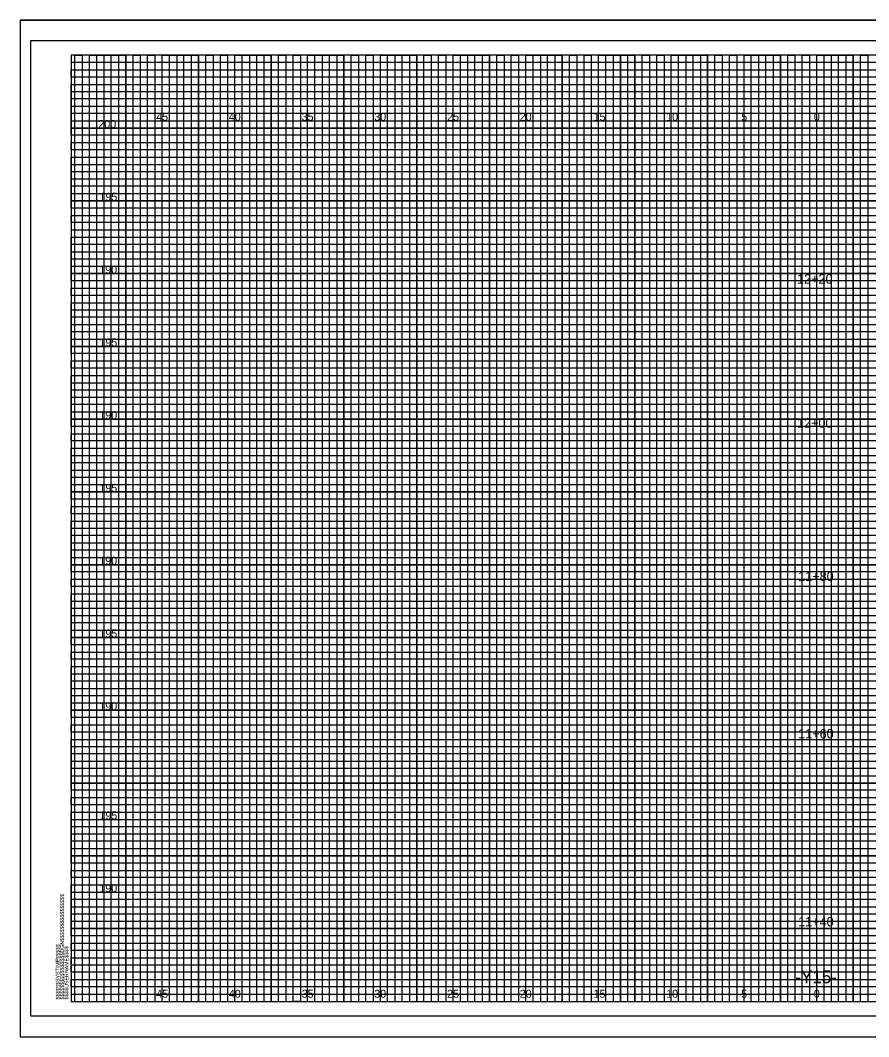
# Model space of a CAD drawing. Extents: x -4 to 103, y -2 to 67.
# Drawn here: x -3.5 to 54.8, y -2.4 to 67.4 of the extents above; entities that cross this region are included whole.
import ezdxf

# ---------------------------------------------------------------- set-up
doc = ezdxf.new("R2010")
doc.units = 0
for name, color, linetype in [('Exist XS Ground Line', 7, 'Continuous'), ('Old_Level_10', 7, 'Continuous'), ('Old_Level_16', 7, 'Continuous'), ('Old_Level_3', 7, 'Continuous'), ('Old_Level_5', 7, 'Continuous'), ('Old_Level_8', 7, 'Continuous'), ('Prop XS Dump Level', 7, 'Continuous'), ('Prop XS EOT Tick Mark', 7, 'Continuous'), ('Prop XS Finish Grade', 7, 'Continuous'), ('Prop XS Side Slope Text', 7, 'Continuous'), ('Prop XS Suitable Common Exc Shape', 7, 'Continuous')]:
    doc.layers.add(name, color=color, linetype=linetype)

msp = doc.modelspace()

# ---------------------------------------------------------------- linework, layer by layer
at = {"layer": 'Exist XS Ground Line'}
msp.add_lwpolyline([(103, 66), (-2.8, 66), (-2.8, -1), (103, -1)], close=True, dxfattribs=at)
at = {"layer": 'Old_Level_10'}
for p, q in [((1.25, 0), (1.25, 65)), ((3.75, 0), (3.75, 65)), ((6.25, 0), (6.25, 65)), ((8.75, 0), (8.75, 65)), ((11.25, 0), (11.25, 65)), ((13.75, 0), (13.75, 65)), ((16.25, 0), (16.25, 65)), ((18.75, 0), (18.75, 65)), ((21.25, 0), (21.25, 65)), ((23.75, 0), (23.75, 65)), ((26.25, 0), (26.25, 65)), ((28.75, 0), (28.75, 65)), ((31.25, 0), (31.25, 65)), ((33.75, 0), (33.75, 65)), ((36.25, 0), (36.25, 65)), ((38.75, 0), (38.75, 65)), ((41.25, 0), (41.25, 65)), ((43.75, 0), (43.75, 65)), ((46.25, 0), (46.25, 65)), ((48.75, 0), (48.75, 65)), ((51.25, 0), (51.25, 65)), ((53.75, 0), (53.75, 65)), ((0, 62.5), (74.25, 62.5)), ((0, 60), (102.5, 60)), ((0, 57.5), (102.5, 57.5)), ((0, 55), (102.5, 55)), ((0, 52.5), (102.5, 52.5)), ((0, 50), (102.5, 50)), ((0, 47.5), (102.5, 47.5)), ((0, 45), (102.5, 45)), ((0, 42.5), (102.5, 42.5)), ((0, 40), (102.5, 40)), ((0, 37.5), (102.5, 37.5)), ((0, 35), (102.5, 35)), ((0, 32.5), (102.5, 32.5)), ((0, 30), (102.5, 30)), ((0, 27.5), (102.5, 27.5)), ((0, 25), (102.5, 25)), ((0, 22.5), (102.5, 22.5)), ((0, 20), (102.5, 20)), ((0, 17.5), (102.5, 17.5)), ((0, 15), (102.5, 15)), ((0, 12.5), (102.5, 12.5)), ((0, 10), (102.5, 10)), ((0, 7.5), (102.5, 7.5)), ((0, 5), (102.5, 5)), ((0, 2.5), (102.5, 2.5))]:
    msp.add_line(p, q, dxfattribs=at)
at = {"layer": 'Old_Level_3'}
for p, q in [((-3.5, 67.4), (103.4, 67.4)), ((-3.5, 67.4), (-3.5, -2.425)), ((-3.5, -2.425), (103.4, -2.425))]:
    msp.add_line(p, q, dxfattribs=at)
at = {"layer": 'Old_Level_5'}
msp.add_lwpolyline([(103.4, 67.4), (-3.5, 67.4), (-3.5, -2.425), (103.4, -2.425)], close=True, dxfattribs=at)
at = {"layer": 'Old_Level_8'}
for points in [[(1.25, 0), (1.25, 65), (3.75, 65), (3.75, 0), (6.25, 0), (6.25, 65), (8.75, 65), (8.75, 0), (11.25, 0), (11.25, 65), (13.75, 65), (13.75, 0), (16.25, 0), (16.25, 65), (18.75, 65), (18.75, 0), (21.25, 0), (21.25, 65), (23.75, 65), (23.75, 0), (26.25, 0), (26.25, 65), (28.75, 65), (28.75, 0), (31.25, 0), (31.25, 65), (33.75, 65), (33.75, 0), (36.25, 0), (36.25, 65), (38.75, 65), (38.75, 0), (41.25, 0), (41.25, 65), (43.75, 65), (43.75, 0), (46.25, 0), (46.25, 65), (48.75, 65), (48.75, 0), (51.25, 0), (51.25, 65), (53.75, 65), (53.75, 0)], [(102.5, 60), (0, 60), (0, 62.5), (74.25, 62.5)], [(102.5, 55), (0, 55), (0, 57.5), (102.5, 57.5)], [(102.5, 50), (0, 50), (0, 52.5), (102.5, 52.5)], [(102.5, 45), (0, 45), (0, 47.5), (102.5, 47.5)], [(102.5, 40), (0, 40), (0, 42.5), (102.5, 42.5)], [(102.5, 35), (0, 35), (0, 37.5), (102.5, 37.5)], [(102.5, 30), (0, 30), (0, 32.5), (102.5, 32.5)], [(102.5, 25), (0, 25), (0, 27.5), (102.5, 27.5)], [(102.5, 20), (0, 20), (0, 22.5), (102.5, 22.5)], [(102.5, 15), (0, 15), (0, 17.5), (102.5, 17.5)], [(102.5, 10), (0, 10), (0, 12.5), (102.5, 12.5)], [(102.5, 5), (0, 5), (0, 7.5), (102.5, 7.5)], [(0, 2.5), (102.5, 2.5)]]:
    msp.add_lwpolyline(points, dxfattribs=at)
at = {"layer": 'Prop XS Dump Level'}
msp.add_lwpolyline([(102.5, 65), (0, 65), (0, 0), (102.5, 0)], close=True, dxfattribs=at)
at = {"layer": 'Prop XS Finish Grade'}
for points in [[(0.25, 0), (0.25, 65), (0.75, 65), (0.75, 0), (1.75, 0), (1.75, 65), (2.25, 65), (2.25, 0), (2.75, 0), (2.75, 65), (3.25, 65), (3.25, 0), (4.25, 0), (4.25, 65), (4.75, 65), (4.75, 0), (5.25, 0), (5.25, 65), (5.75, 65), (5.75, 0), (6.75, 0), (6.75, 65), (7.25, 65), (7.25, 0), (7.75, 0), (7.75, 65), (8.25, 65), (8.25, 0), (9.25, 0), (9.25, 65), (9.75, 65), (9.75, 0), (10.25, 0), (10.25, 65), (10.75, 65), (10.75, 0), (11.75, 0), (11.75, 65), (12.25, 65), (12.25, 0), (12.75, 0), (12.75, 65), (13.25, 65), (13.25, 0), (14.25, 0), (14.25, 65), (14.75, 65), (14.75, 0), (15.75, 0), (15.25, 0), (15.25, 65), (15.75, 65), (15.75, 0), (16.75, 0), (16.75, 65), (17.25, 65), (17.25, 0), (17.75, 0), (17.75, 65), (18.25, 65), (18.25, 0), (19.25, 0), (19.25, 65), (19.75, 65), (19.75, 0), (20.25, 0), (20.25, 65), (20.75, 65), (20.75, 0), (21.75, 0), (21.75, 65), (22.25, 65), (22.25, 0), (22.75, 0), (22.75, 65), (23.25, 65), (23.25, 0), (24.25, 0), (24.25, 65), (24.75, 65), (24.75, 0), (25.25, 0), (25.25, 65), (25.75, 65), (25.75, 0), (26.75, 0), (26.75, 65), (27.25, 65), (27.25, 0), (27.75, 0), (27.75, 65), (28.25, 65), (28.25, 0), (29.25, 0), (29.25, 65), (29.75, 65), (29.75, 0), (30.25, 0), (30.25, 65), (30.75, 65), (30.75, 0)], [(30.75, 0), (31.75, 0), (31.75, 65), (32.25, 65), (32.25, 0), (32.75, 0), (32.75, 65), (33.25, 65), (33.25, 0), (34.25, 0), (34.25, 65), (34.75, 65), (34.75, 0), (35.25, 0), (35.25, 65), (35.75, 65), (35.75, 0), (36.75, 0), (36.75, 65), (37.25, 65), (37.25, 0), (37.75, 0), (37.75, 65), (37.75, 0)], [(38.25, 65), (38.25, 0), (39.25, 0), (39.25, 65), (39.75, 65), (39.75, 0), (40.25, 0), (40.25, 65), (40.75, 65), (40.75, 0), (41.75, 0), (41.75, 65), (42.25, 65), (42.25, 0), (42.75, 0), (42.75, 65), (43.25, 65), (43.25, 0), (43.75, 0), (44.25, 0), (44.25, 65), (44.75, 65), (44.75, 0), (45.25, 0), (45.25, 65), (45.75, 65), (45.75, 0), (46.75, 0), (46.75, 65), (47.25, 65), (47.25, 0), (47.75, 0), (47.75, 65), (48.25, 65), (48.25, 0), (49.25, 0), (49.25, 65), (49.75, 65), (49.75, 0), (50.25, 0), (50.25, 65), (50.75, 65), (50.75, 0), (51.75, 0), (51.75, 65), (52.25, 65), (52.25, 0), (52.75, 0), (52.75, 65), (53.25, 65), (53.25, 0), (54.25, 0), (54.25, 65), (54.75, 65), (54.75, 0), (55.25, 0)], [(0, 62), (0, 63), (74.25, 63), (74.25, 63.5), (0, 63.5), (0, 64), (74.25, 64), (74.25, 64.5), (0, 64.5)], [(102.5, 62), (0, 62)], [(102.5, 61), (0, 61), (0, 61.5), (102.5, 61.5)], [(102.5, 59.5), (0, 59.5), (0, 60.5), (102.5, 60.5)], [(102.5, 58.5), (0, 58.5), (0, 59), (102.5, 59)], [(102.5, 57), (0, 57), (0, 58), (102.5, 58)], [(102.5, 56), (0, 56), (0, 56.5), (102.5, 56.5)], [(102.5, 54.5), (0, 54.5), (0, 55.5), (102.5, 55.5)], [(102.5, 53.5), (0, 53.5), (0, 54), (102.5, 54)], [(0, 53), (102.5, 53)], [(102.5, 52), (0, 52)], [(102.5, 51), (0, 51), (0, 51.5), (102.5, 51.5)], [(102.5, 49.5), (0, 49.5), (0, 50.5), (102.5, 50.5)], [(102.5, 48.5), (0, 48.5), (0, 49), (102.5, 49)], [(102.5, 47), (0, 47), (0, 48), (102.5, 48)], [(102.5, 46), (0, 46), (0, 46.5), (102.5, 46.5)], [(102.5, 44.5), (0, 44.5), (0, 45.5), (102.5, 45.5)], [(102.5, 43.5), (0, 43.5), (0, 44), (102.5, 44)], [(102.5, 42), (0, 42), (0, 43), (102.5, 43)], [(102.5, 41), (0, 41), (0, 41.5), (102.5, 41.5)], [(102.5, 39.5), (0, 39.5), (0, 40.5), (102.5, 40.5)], [(102.5, 38.5), (0, 38.5), (0, 39), (102.5, 39)], [(102.5, 37), (0, 37), (0, 38), (102.5, 38)], [(102.5, 36), (0, 36), (0, 36.5), (102.5, 36.5)], [(102.5, 34.5), (0, 34.5), (0, 35.5), (102.5, 35.5)], [(102.5, 33.5), (0, 33.5), (0, 34), (102.5, 34)], [(102.5, 32), (0, 32), (0, 33), (102.5, 33)], [(102.5, 31), (0, 31), (0, 31.5)], [(0, 31.5), (102.5, 31.5)], [(102.5, 29.5), (0, 29.5), (0, 30.5), (102.5, 30.5)], [(102.5, 28.5), (0, 28.5), (0, 29), (102.5, 29)], [(102.5, 27), (0, 27), (0, 28), (102.5, 28)], [(102.5, 26), (0, 26), (0, 26.5), (102.5, 26.5)], [(102.5, 24.5), (0, 24.5), (0, 25.5), (102.5, 25.5)], [(102.5, 23.5), (0, 23.5), (0, 24), (102.5, 24)], [(102.5, 22), (0, 22), (0, 23), (102.5, 23)], [(102.5, 21), (0, 21), (0, 21.5), (102.5, 21.5)], [(102.5, 19.5), (0, 19.5), (0, 20.5), (102.5, 20.5)], [(102.5, 18.5), (0, 18.5), (0, 19), (102.5, 19)], [(102.5, 17), (0, 17), (0, 18), (102.5, 18)], [(102.5, 16), (0, 16), (0, 16.5), (102.5, 16.5)], [(102.5, 14.5), (0, 14.5), (0, 15.5), (102.5, 15.5)], [(102.5, 13.5), (0, 13.5), (0, 14), (102.5, 14)], [(102.5, 12), (0, 12), (0, 13), (102.5, 13)], [(102.5, 11), (0, 11), (0, 11.5), (102.5, 11.5)], [(102.5, 9.5), (0, 9.5), (0, 10.5), (102.5, 10.5)], [(102.5, 8.5), (0, 8.5), (0, 9), (102.5, 9)], [(102.5, 7), (0, 7), (0, 8), (102.5, 8)], [(102.5, 6), (0, 6), (0, 6.5), (102.5, 6.5)], [(102.5, 4.5), (0, 4.5), (0, 5.5), (102.5, 5.5)], [(102.5, 3.5), (0, 3.5), (0, 4), (102.5, 4)], [(102.5, 2), (0, 2), (0, 3), (102.5, 3)], [(102.5, 1), (0, 1), (0, 1.5), (102.5, 1.5)], [(0, 0.5), (102.5, 0.5)]]:
    msp.add_lwpolyline(points, dxfattribs=at)

# ---------------------------------------------------------------- texts
at = {"layer": 'Old_Level_16'}
for s, p in [('45', (5.8399, 60.5)), ('40', (10.8313, 60.5)), ('35', (15.8399, 60.5)), ('30', (20.8313, 60.5)), ('25', (25.8399, 60.5)), ('20', (30.8313, 60.5)), ('15', (35.9058, 60.5)), ('10', (40.8971, 60.5)), ('5', (46.0574, 60.5)), ('0', (51.0488, 60.5)), ('0', (51.0488, 60.5)), ('45', (5.8399, 0.25)), ('40', (10.8313, 0.25)), ('35', (15.8399, 0.25)), ('30', (20.8313, 0.25)), ('25', (25.8399, 0.25)), ('20', (30.8313, 0.25)), ('15', (35.9058, 0.25)), ('10', (40.8971, 0.25)), ('5', (46.0574, 0.25)), ('0', (51.0488, 0.25)), ('0', (51.0488, 0.25))]:
    msp.add_text(s, height=0.55, dxfattribs=at).set_placement(p)
at = {"layer": 'Old_Level_8'}
msp.add_text('040397', height=0.0025, rotation=90, dxfattribs=at).set_placement((-0.0007, 64.9864))
at = {"layer": 'Prop XS Dump Level'}
for s, p in [('$$$$$$$$$$$$$$$$DGN$$$$$$$$$$$$$$$$', (-0.5, 0.125)), ('$$$$$$SYSTIME$$$$$', (-0.7973, 0.1247)), ('$$$$USERNAME$$$$', (-0.2, 0.125))]:
    msp.add_text(s, height=0.2625, rotation=90, dxfattribs=at).set_placement(p)
at = {"layer": 'Prop XS EOT Tick Mark'}
msp.add_text('-Y15-', height=0.875, dxfattribs=at).set_placement((49.7731, 1.25))
at = {"layer": 'Prop XS Side Slope Text'}
for s, p in [('12+20', (49.8934, 49.308)), ('12+00', (49.8934, 39.4163)), ('11+80', (49.9712, 28.8737)), ('11+60', (49.9712, 18.066)), ('11+40', (49.9712, 5.1512))]:
    msp.add_text(s, height=0.65, dxfattribs=at).set_placement(p)
at = {"layer": 'Prop XS Suitable Common Exc Shape'}
for s, p in [('200', (1.8638, 60)), ('195', (1.9383, 55)), ('190', (1.9296, 50)), ('195', (1.9383, 45)), ('190', (1.9296, 40)), ('195', (1.9383, 35)), ('190', (1.9296, 30)), ('195', (1.9383, 25)), ('190', (1.9296, 20)), ('195', (1.9383, 12.5)), ('190', (1.9296, 7.5))]:
    msp.add_text(s, height=0.55, dxfattribs=at).set_placement(p)

doc.saveas('drawing.dxf')
